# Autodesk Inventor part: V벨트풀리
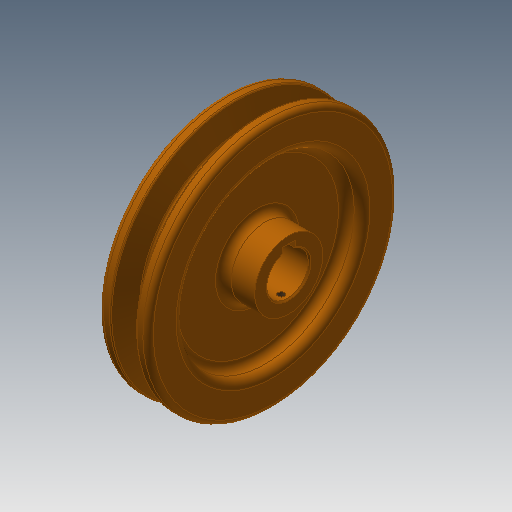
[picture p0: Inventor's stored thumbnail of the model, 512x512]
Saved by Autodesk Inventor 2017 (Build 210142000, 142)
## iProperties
Created: 2015-11
Part Number: V벨트풀리
Material: 강철, 탄소
Document SubType Name: Modeling
Designer: mduedu
Density: 1 g/cm^3
Appearance: 주황색
Author: mduedu
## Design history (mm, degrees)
sketch "스케치1"
  geometry: L1 (-9.5, 0)-(9.5, 0); L2 (0, 0)-(0, 47.7); L3 (-4.877, 47.7)-(-9.5, 47.7); L4 (-9.5, 47.7)-(-9.5, 0); L5 (0, 38.7)-(-1.953, 38.7); L6 (-1.953, 38.7)-(-4.877, 47.7); L7 (4.877, 47.7)-(9.5, 47.7); L8 (9.5, 47.7)-(9.5, 0); L9 (0, 38.7)-(1.953, 38.7); L10 (1.953, 38.7)-(4.877, 47.7); L11 (-9.5, 45)-(9.5, 45); 3 further points
  constraints: 22 end point, 7 point on line, 4 perpendicular, 3 symmetric about line, 1 coincident, 1 horizontal, 1 horizontal alignment, 1 midpoint, 1 vertical
  dimensions: "d0" = 19 distance of L1.start L1.end; "d2" = 95.4 diameter of L2.end L1 (derived); "d3" = 36 deg angle of L10 L6; "d4" = 6.3 distance between parallel lines of L11 L9; "d5" = 2.7 distance between parallel lines of L7 L11; "d6" = 8 distance of point (4, 45) point (-4, 45); "d7" = 90 diameter of L11 L1
revolve "회전1" sketch "스케치1" stored, may be unused: angle "d8" = 90 deg
sketch "스케치2"
  geometry: C1 r 34 at (0, 0); C2 r 13 at (0, 0); 1 further point
  constraints: 2 centre point, 2 coincident
  dimensions: "d9" = 68 diameter of C1; "d10" = 26 diameter of C2
extrude "돌출1" cut sketch "스케치2" distance "d11" = 6; taper "d12" = 0 deg
extrude "돌출3" join sketch "스케치2" distance "d37" = 6; taper "d38" = 0 deg
fillet "모깎기1" dims "d13" = 3
fillet "모깎기2" dims "d14" = 3
fillet "모깎기3" dims "d15" = 1, "d16" = 0.5, "d17" = 2
hole "구멍1" diameter "d20" = 16; stored, may be unused: countersink angle "d24" = 90 deg, drill point angle "d26" = 118 deg; dims "d21" = 6, "d22" = 4, "d23" = 2, "d25" = 8, "d53" = 10, "d54" = 10
sketch "스케치3"
  geometry: L1 (-2.5, 0)-(2.5, 0); L2 (2.5, 0)-(2.5, 10.3); L3 (2.5, 10.3)-(-2.5, 10.3); L4 (-2.5, 10.3)-(-2.5, 0); 2 further points
  constraints: 8 end point, 2 parallel, 1 coincident, 1 horizontal, 1 midpoint, 1 perpendicular
  dimensions: "d27" = 5 distance of L2.end L3.end; "d29" = 10.3 distance of L3.end L1.start
extrude "돌출2" cut sketch "스케치3" stored distance "d30" = 6; taper "d31" = 0 deg
node "작업 평면1"
sketch "스케치4"
  geometry: L1 (19, -37)-(19, 37) reference; 2 further points
  constraints: 1 horizontal alignment
  dimensions: "d52" = 22 distance from line of L1 point (-3, 0)
hole "구멍2" sketch "스케치4" at (-3, 0) diameter "d42" = 2.459; stored, may be unused: countersink angle "d46" = 90 deg, drill point angle "d48" = 118 deg; dims "d43" = 6, "d44" = 4, "d45" = 2, "d47" = 8
chamfer "모따기3" distance "d58" = 0.5; stored, may be unused: second distance "d59" = 2, angle "d60" = 45 deg
node "솔리드1"
mirror "대칭1"
